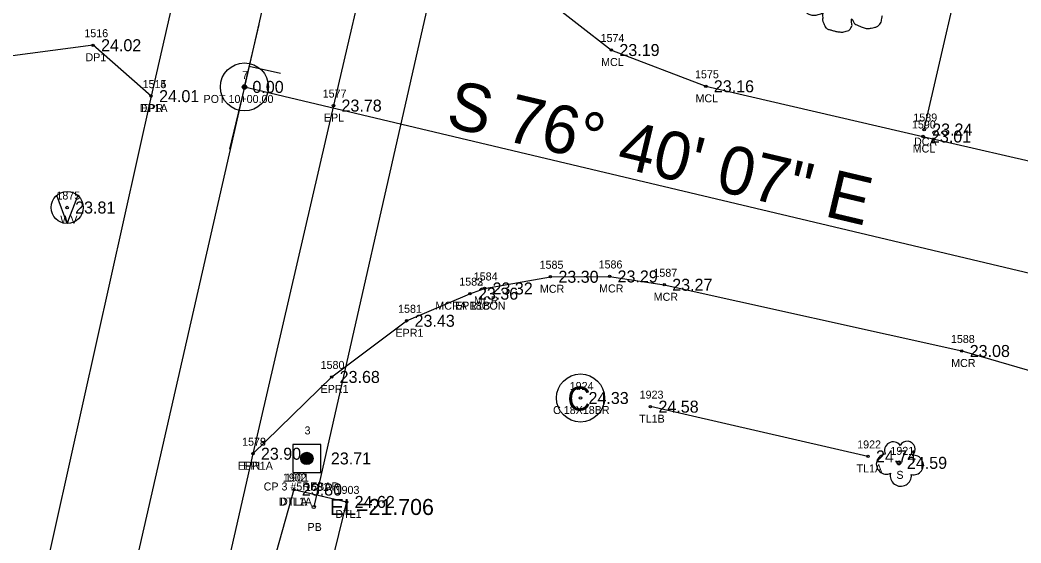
# Model space of a CAD drawing. Extents: x 2654414 to 2656963, y 761776 to 764965.
# Drawn here: x 2655582.6 to 2655707.7, y 762727.3 to 762792.6 of the extents above; entities that cross this region are included whole.
import ezdxf

# ---------------------------------------------------------------- set-up
doc = ezdxf.new("R2010")
doc.units = 0
for name, color, linetype in [('Default', 7, 'Continuous'), ('RD_EX_BldgApp', 7, 'Continuous'), ('RD_EX_BldgApp_txCode', 7, 'Continuous'), ('RD_EX_Conc', 7, 'Continuous'), ('RD_EX_Conc_txCode', 7, 'Continuous'), ('RD_EX_DR_Pipe', 7, 'Continuous'), ('RD_EX_DR_Pipe_txCode', 7, 'Continuous'), ('RD_EX_Driveway', 7, 'Continuous'), ('RD_EX_Driveway_txCode', 7, 'Continuous'), ('RD_EX_H2O', 7, 'Continuous'), ('RD_EX_H2O_txCode', 7, 'Continuous'), ('RD_EX_Road', 7, 'Continuous'), ('RD_EX_Road_txCode', 7, 'Continuous'), ('RD_EX_TX_BldgApp_ELEV', 7, 'Continuous'), ('RD_EX_TX_Conc_ELEV', 7, 'Continuous'), ('RD_EX_TX_Driveway_ELEV', 7, 'Continuous'), ('RD_EX_TX_H2O_ELEV', 7, 'Continuous'), ('RD_EX_TX_Road_ELEV', 7, 'Continuous'), ('RD_EX_TX_UT_ELEV', 7, 'Continuous'), ('RD_EX_TX_VEG_ELEV', 7, 'Continuous'), ('RD_EX_UT', 7, 'Continuous'), ('RD_EX_UT_txCode', 7, 'Continuous'), ('RD_EX_VEG', 7, 'Continuous'), ('RD_EX_VEG_txCode', 7, 'Continuous'), ('RD_HC_Cl', 7, 'Continuous'), ('RD_HC_Data', 7, 'Continuous'), ('RD_HC_Data_Tic', 7, 'Continuous'), ('RD_HC_Survey', 7, 'Continuous'), ('RD_HC_Survey_ELEV', 7, 'Continuous'), ('RD_HC_Survey_txCode', 7, 'Continuous'), ('RD_HC_txCode', 7, 'Continuous'), ('RD_SMD_Locator', 7, 'Continuous'), ('RD_TX_Pipe_ElevEX', 7, 'Continuous')]:
    doc.layers.add(name, color=color, linetype=linetype)

msp = doc.modelspace()

# ---------------------------------------------------------------- linework, layer by layer
at = {"layer": 'Default'}
msp.add_line((2656050.51, 764712.37), (2655383.26, 761787.51), dxfattribs=at)
at = {"layer": 'RD_EX_BldgApp'}
msp.add_circle((2655652.64, 762745.39), 3, dxfattribs=at)
at = {"layer": 'RD_EX_Conc'}
for points in [[(2655695.58, 762778.92), (2655701.44, 762804.38), (2655697.59, 762810.88), (2655698.83, 762816.69)], [(2655647.95, 762795.55), (2655656.5, 762788.85), (2655668.3, 762784.32), (2655695.43, 762778.05), (2655712.44, 762774.14), (2655737.03, 762767.62), (2655754.84, 762760.94), (2655757.41, 762759.82), (2655785.93, 762744.56)], [(2655638.83, 762758.42), (2655640.65, 762759.07), (2655648.88, 762760.53), (2655656.27, 762760.57), (2655663.1, 762759.53), (2655700.27, 762751.26), (2655744.39, 762738.46), (2655772.67, 762723.5), (2655774.32, 762722.61)]]:
    msp.add_lwpolyline(points, dxfattribs=at)
at = {"layer": 'RD_EX_DR_Pipe'}
msp.add_line((2655640.05, 762823.04), (2655619.31, 762731.78), dxfattribs=at)
at = {"layer": 'RD_EX_Driveway'}
msp.add_lwpolyline([(2655598.99, 762783.09), (2655591.74, 762789.45), (2655575.98, 762787.38), (2655565.19, 762780.33), (2655555.27, 762759.9), (2655550.24, 762730.01), (2655544.34, 762701.07), (2655531.32, 762637.94), (2655527.7, 762630.48), (2655527.21, 762614.18), (2655533.68, 762601.37), (2655541.26, 762592.29), (2655549.19, 762591.56), (2655556.36, 762593.84)], dxfattribs=at)
at = {"layer": 'RD_EX_H2O'}
for points in [[(2655616.83, 762733.96), (2655623.42, 762732.41), (2655617.05, 762706.39), (2655607.13, 762649.27), (2655597.13, 762609.55), (2655592.83, 762601.92), (2655590.72, 762602.48), (2655588.85, 762603.42), (2655588.37, 762607.98)], [(2655616.83, 762733.96), (2655609.4, 762707.61), (2655588.37, 762607.98)]]:
    msp.add_lwpolyline(points, dxfattribs=at)
at = {"layer": 'RD_EX_Road'}
for points in [[(2655700.99, 763232.28), (2655693.55, 763198.57), (2655671.65, 763102.04), (2655649.04, 763001.06), (2655627.27, 762906.23), (2655605, 762809.37), (2655598.99, 762783.09), (2655583.65, 762714.14), (2655561.97, 762618.32), (2655556.36, 762593.84), (2655548.11, 762557.14), (2655540.1, 762522.48), (2655518.03, 762425.04), (2655496.48, 762329.56), (2655475.55, 762236.62), (2655473.2, 762226.14), (2655466.57, 762197.5), (2655460.06, 762168.16), (2655454.26, 762143.78), (2655432.5, 762049.88), (2655410.7, 761955.51), (2655388.17, 761858.43), (2655373.5, 761793.95)], [(2655670.04, 762995.18), (2655648.57, 762900.67), (2655631.27, 762824.03), (2655626.67, 762802.87), (2655621.78, 762781.91), (2655611.71, 762738.43), (2655604.93, 762708.62), (2655582.64, 762610.54), (2655576.46, 762583.32), (2655561.41, 762517.24), (2655539.15, 762414.81), (2655531.98, 762386.15), (2655517.98, 762324.29), (2655508.17, 762280.15), (2655501.46, 762251.6), (2655496.92, 762232.09), (2655477.2, 762144.97), (2655472.14, 762122.52), (2655453.74, 762045.1), (2655431.79, 761949.92), (2655409.76, 761853.25), (2655401.25, 761816.42), (2655394.61, 761787.37)], [(2655611.71, 762738.43), (2655621.55, 762748.02), (2655630.91, 762755.03), (2655638.83, 762758.42)]]:
    msp.add_lwpolyline(points, dxfattribs=at)
at = {"layer": 'RD_EX_UT'}
for q in [(2655587.2, 762770.67), (2655589.82, 762770.64)]:
    msp.add_line((2655588.5, 762767.19), q, dxfattribs=at)
msp.add_circle((2655588.5, 762769.18), 2, dxfattribs=at)
at = {"layer": 'RD_EX_VEG'}
msp.add_line((2655688.56, 762738.09), (2655661.38, 762744.31), dxfattribs=at)
msp.add_circle((2655692.42, 762737.29), 0.25, dxfattribs=at)
for centre, radius, start, end in [((2655691.7, 762738.83), 1.08, 34.9763, 204.756), ((2655693.46, 762738.99), 0.995, 308.7626, 152.0467), ((2655690.86, 762737.13), 1.26, 96.4518, 294.734), ((2655694.26, 762737.01), 1.22, 256.5667, 98.1046), ((2655692.66, 762735.69), 1.32, 166.8827, 5.7589)]:
    msp.add_arc(centre, radius, start, end, dxfattribs=at)
msp.add_spline([(2655686.15, 762805.66), (2655685.85, 762805.69), (2655685.52, 762805.59), (2655685.27, 762805.49), (2655685.05, 762805.41), (2655684.82, 762805.31), (2655684.52, 762805.14), (2655684.3, 762804.94), (2655684.17, 762804.69), (2655684.12, 762804.46), (2655684.07, 762804.19), (2655684.07, 762804.01), (2655683.95, 762803.99), (2655683.8, 762804.01), (2655683.55, 762804.09), (2655683.3, 762804.09), (2655683.05, 762804.09), (2655682.7, 762804.06), (2655682.35, 762804.06), (2655682.08, 762804.01), (2655681.75, 762803.96), (2655681.38, 762803.84), (2655681.03, 762803.71), (2655680.73, 762803.46), (2655680.48, 762802.99), (2655680.35, 762802.64), (2655680.2, 762802.39), (2655680.35, 762801.94), (2655680.53, 762801.59), (2655680.55, 762801.39), (2655680.63, 762800.96), (2655680.73, 762800.74), (2655680.85, 762800.54), (2655680.78, 762800.51), (2655680.4, 762800.46), (2655680.1, 762800.36), (2655679.68, 762800.14), (2655679.45, 762799.91), (2655679.35, 762799.59), (2655679.33, 762799.24), (2655679.23, 762799.04), (2655679.15, 762798.76), (2655679.13, 762798.69), (2655679.08, 762798.36), (2655679.18, 762797.91), (2655679.2, 762797.56), (2655679.33, 762797.34), (2655679.48, 762797.16), (2655679.65, 762796.91), (2655680.05, 762796.69), (2655680.38, 762796.59), (2655680.58, 762796.56), (2655680.4, 762796.06), (2655680.35, 762795.71), (2655680.23, 762795.32), (2655680.23, 762795.24), (2655680.18, 762794.77), (2655680.33, 762794.44), (2655680.4, 762794.07), (2655680.58, 762793.84), (2655680.85, 762793.54), (2655681.18, 762793.32), (2655681.68, 762793.19), (2655682.08, 762793.22), (2655682.65, 762793.39), (2655682.9, 762793.47), (2655682.88, 762793.29), (2655682.9, 762792.92), (2655682.9, 762792.49), (2655683.05, 762792.17), (2655683.15, 762791.89), (2655683.3, 762791.64), (2655683.63, 762791.42), (2655684.02, 762791.34), (2655684.45, 762791.19), (2655684.9, 762791.12), (2655685.4, 762791.09), (2655686, 762791.24), (2655686.27, 762791.37), (2655686.37, 762791.54), (2655686.57, 762791.92), (2655686.52, 762792.14), (2655686.55, 762792.74), (2655686.65, 762792.57), (2655686.82, 762792.22), (2655687.32, 762791.92), (2655687.72, 762791.74), (2655688.2, 762791.59), (2655688.5, 762791.52), (2655688.97, 762791.59), (2655689.35, 762791.67), (2655689.72, 762791.79), (2655690.02, 762792.07), (2655690.2, 762792.34), (2655690.25, 762792.62), (2655690.32, 762792.99), (2655690.37, 762793.17)], degree=3, dxfattribs=at)
at = {"layer": 'RD_HC_Cl'}
for p, q in [((2656050.51, 764712.37), (2655383.26, 761787.51)), ((2655610.65, 762784.24), (2655716.3, 762759.21))]:
    msp.add_line(p, q, dxfattribs=at)
at = {"layer": 'RD_HC_Data'}
for radius in [3, 0.282]:
    msp.add_circle((2655610.65, 762784.24), radius, dxfattribs=at)
at = {"layer": 'RD_HC_Data_Tic'}
for p, q in [((2655610.65, 762784.24), (2655612.49, 762792.03)), ((2655611.24, 762786.84), (2655615.14, 762785.95)), ((2655610.65, 762784.24), (2655608.8, 762776.46))]:
    msp.add_line(p, q, dxfattribs=at)
at = {"layer": 'RD_HC_Survey'}
for p, q in [((2655617.7, 762737.66), (2655617.7, 762738.02)), ((2655617.72, 762737.58), (2655617.72, 762738.1)), ((2655617.75, 762737.52), (2655617.75, 762738.16)), ((2655617.77, 762737.47), (2655617.77, 762738.21)), ((2655617.8, 762737.43), (2655617.8, 762738.25)), ((2655617.82, 762737.39), (2655617.82, 762738.29)), ((2655617.85, 762737.36), (2655617.85, 762738.32)), ((2655617.87, 762737.33), (2655617.87, 762738.35)), ((2655617.9, 762737.3), (2655617.9, 762738.38)), ((2655617.92, 762737.28), (2655617.92, 762738.4)), ((2655617.95, 762737.25), (2655617.95, 762738.42)), ((2655617.97, 762737.23), (2655617.97, 762738.44)), ((2655618, 762737.22), (2655618, 762738.46)), ((2655618.02, 762737.2), (2655618.02, 762738.48)), ((2655618.05, 762737.18), (2655618.05, 762738.5)), ((2655618.07, 762737.17), (2655618.07, 762738.51)), ((2655618.09, 762737.16), (2655618.09, 762738.52)), ((2655618.12, 762737.14), (2655618.12, 762738.54)), ((2655618.14, 762737.13), (2655618.14, 762738.55)), ((2655618.17, 762737.12), (2655618.17, 762738.56)), ((2655618.19, 762737.11), (2655618.19, 762738.57)), ((2655618.22, 762737.1), (2655618.22, 762738.57)), ((2655618.24, 762737.1), (2655618.24, 762738.58)), ((2655618.27, 762737.09), (2655618.27, 762738.59)), ((2655618.29, 762737.09), (2655618.29, 762738.59)), ((2655618.32, 762737.08), (2655618.32, 762738.6)), ((2655618.34, 762737.08), (2655618.34, 762738.6)), ((2655618.37, 762737.07), (2655618.37, 762738.6)), ((2655618.39, 762737.07), (2655618.39, 762738.61)), ((2655618.42, 762737.07), (2655618.42, 762738.61)), ((2655618.44, 762737.07), (2655618.44, 762738.61)), ((2655618.47, 762737.07), (2655618.47, 762738.61)), ((2655618.49, 762737.07), (2655618.49, 762738.61)), ((2655618.52, 762737.07), (2655618.52, 762738.61)), ((2655618.54, 762737.08), (2655618.54, 762738.6)), ((2655618.56, 762737.08), (2655618.56, 762738.6)), ((2655618.59, 762737.08), (2655618.59, 762738.6)), ((2655618.61, 762737.09), (2655618.61, 762738.59)), ((2655618.64, 762737.09), (2655618.64, 762738.58)), ((2655618.66, 762737.1), (2655618.66, 762738.58)), ((2655618.69, 762737.11), (2655618.69, 762738.57)), ((2655618.71, 762737.12), (2655618.71, 762738.56)), ((2655618.74, 762737.13), (2655618.74, 762738.55)), ((2655618.76, 762737.14), (2655618.76, 762738.54)), ((2655618.79, 762737.15), (2655618.79, 762738.53)), ((2655618.81, 762737.16), (2655618.81, 762738.52)), ((2655618.84, 762737.18), (2655618.84, 762738.5)), ((2655618.86, 762737.19), (2655618.86, 762738.49)), ((2655618.89, 762737.21), (2655618.89, 762738.47)), ((2655618.91, 762737.23), (2655618.91, 762738.45)), ((2655618.94, 762737.25), (2655618.94, 762738.43)), ((2655618.96, 762737.27), (2655618.96, 762738.41)), ((2655618.99, 762737.29), (2655618.99, 762738.39)), ((2655619.01, 762737.31), (2655619.01, 762738.36)), ((2655619.04, 762737.34), (2655619.04, 762738.34)), ((2655619.06, 762737.37), (2655619.06, 762738.3)), ((2655619.08, 762737.41), (2655619.08, 762738.27)), ((2655619.11, 762737.45), (2655619.11, 762738.23)), ((2655619.13, 762737.49), (2655619.13, 762738.19)), ((2655619.16, 762737.55), (2655619.16, 762738.13)), ((2655619.18, 762737.62), (2655619.18, 762738.06)), ((2655619.21, 762737.73), (2655619.21, 762737.95))]:
    msp.add_line(p, q, dxfattribs=at)
msp.add_lwpolyline([(2655620.2, 762739.59), (2655616.7, 762739.59), (2655616.7, 762736.09), (2655620.2, 762736.09)], close=True, dxfattribs=at)
msp.add_circle((2655618.45, 762737.84), 0.769, dxfattribs=at)
at = {"layer": 'RD_SMD_Locator'}
for centre, radius in [((2655591.74, 762789.45), 0.15), ((2655656.5, 762788.85), 0.15), ((2655610.65, 762784.24), 0.15), ((2655668.3, 762784.32), 0.15), ((2655598.99, 762783.09), 0.15), ((2655598.99, 762783.09), 0.15), ((2655621.78, 762781.91), 0.15), ((2655695.58, 762778.92), 0.15), ((2655695.43, 762778.05), 0.15), ((2655588.5, 762769.18), 0.15), ((2655648.88, 762760.53), 0.15), ((2655656.27, 762760.57), 0.15), ((2655640.65, 762759.07), 0.15), ((2655663.1, 762759.53), 0.15), ((2655638.83, 762758.42), 0.15), ((2655638.83, 762758.42), 0.15), ((2655630.91, 762755.03), 0.15), ((2655700.27, 762751.26), 0.15), ((2655621.55, 762748.02), 0.15), ((2655652.64, 762745.39), 0.15), ((2655661.38, 762744.31), 0.15), ((2655611.71, 762738.43), 0.15), ((2655611.71, 762738.43), 0.15), ((2655618.45, 762737.84), 0.15), ((2655688.56, 762738.09), 0.15), ((2655692.42, 762737.29), 0.15), ((2655616.83, 762733.96), 0.15), ((2655616.83, 762733.96), 0.15), ((2655623.42, 762732.41), 0.15), ((2655619.31, 762731.78), 0.2)]:
    msp.add_circle(centre, radius, dxfattribs=at)

# ---------------------------------------------------------------- texts
at = {"layer": 'RD_EX_BldgApp'}
msp.add_text('C', height=3, dxfattribs=at).set_placement((2655651.01, 762743.82))
at = {"layer": 'RD_EX_BldgApp_txCode'}
for s, p in [('1924', (2655651.29, 762746.39)), ('C 18X18BR', (2655649.21, 762743.39))]:
    msp.add_text(s, height=1, dxfattribs=at).set_placement(p)
at = {"layer": 'RD_EX_Conc_txCode'}
for s, p in [('1574', (2655655.15, 762789.85)), ('MCL', (2655655.21, 762786.85)), ('1575', (2655666.95, 762785.32)), ('MCL', (2655667.01, 762782.32)), ('1590', (2655694.05, 762779.05)), ('1589', (2655694.23, 762779.92)), ('DCA', (2655694.31, 762776.92)), ('MCL', (2655694.14, 762776.05)), ('1585', (2655647.53, 762761.53)), ('1586', (2655654.9, 762761.57)), ('1587', (2655661.75, 762760.53)), ('1583', (2655637.49, 762759.42)), ('1584', (2655639.3, 762760.07)), ('MCR', (2655647.57, 762758.53)), ('MCR', (2655654.96, 762758.57)), ('MCRA 18CON', (2655634.5, 762756.42)), ('MCR', (2655639.34, 762757.07)), ('MCR', (2655661.78, 762757.53)), ('1588', (2655698.92, 762752.26)), ('MCR', (2655698.95, 762749.26))]:
    msp.add_text(s, height=1, dxfattribs=at).set_placement(p)
at = {"layer": 'RD_EX_DR_Pipe_txCode'}
for s, p in [('1631', (2655618.22, 762733.78)), ('PB', (2655618.53, 762728.78))]:
    msp.add_text(s, height=1, dxfattribs=at).set_placement(p)
at = {"layer": 'RD_EX_Driveway_txCode'}
for s, p in [('1516', (2655590.65, 762790.45)), ('DP1', (2655590.79, 762787.45)), ('1515', (2655597.93, 762784.09)), ('DP1A', (2655597.56, 762781.09))]:
    msp.add_text(s, height=1, dxfattribs=at).set_placement(p)
at = {"layer": 'RD_EX_H2O_txCode'}
for s, p in [('1902', (2655615.45, 762734.96)), ('1901', (2655615.73, 762734.96)), ('1903', (2655622.04, 762733.41)), ('DTL1A', (2655614.93, 762731.96)), ('DTLA', (2655615.1, 762731.96)), ('DTL1', (2655622.01, 762730.41))]:
    msp.add_text(s, height=1, dxfattribs=at).set_placement(p)
at = {"layer": 'RD_EX_Road_txCode'}
for s, p in [('1514', (2655597.93, 762784.09)), ('1577', (2655620.43, 762782.91)), ('EPR', (2655597.76, 762781.09)), ('EPL', (2655620.58, 762779.91)), ('1582', (2655637.49, 762759.42)), ('EPR1B', (2655636.97, 762756.42)), ('1581', (2655629.85, 762756.03)), ('EPR1', (2655629.52, 762753.03)), ('1580', (2655620.17, 762749.02)), ('EPR1', (2655620.16, 762746.02)), ('1578', (2655610.36, 762739.43)), ('1579', (2655610.36, 762739.43)), ('EPR1A', (2655609.82, 762736.43)), ('EPL', (2655610.5, 762736.43))]:
    msp.add_text(s, height=1, dxfattribs=at).set_placement(p)
at = {"layer": 'RD_EX_TX_BldgApp_ELEV'}
msp.add_text('24.33', height=1.5, dxfattribs=at).set_placement((2655653.64, 762744.64))
at = {"layer": 'RD_EX_TX_Conc_ELEV'}
for s, p in [('23.19', (2655657.5, 762788.1)), ('23.16', (2655669.3, 762783.57)), ('23.01', (2655696.43, 762777.3)), ('23.24', (2655696.58, 762778.17)), ('23.30', (2655649.88, 762759.78)), ('23.29', (2655657.27, 762759.82)), ('23.27', (2655664.1, 762758.78)), ('23.36', (2655639.83, 762757.67)), ('23.32', (2655641.65, 762758.32)), ('23.08', (2655701.27, 762750.51))]:
    msp.add_text(s, height=1.5, dxfattribs=at).set_placement(p)
at = {"layer": 'RD_EX_TX_Driveway_ELEV'}
for s, p in [('24.02', (2655592.74, 762788.7)), ('24.01', (2655599.99, 762782.34))]:
    msp.add_text(s, height=1.5, dxfattribs=at).set_placement(p)
at = {"layer": 'RD_EX_TX_H2O_ELEV'}
for s, p in [('23.80', (2655617.83, 762733.21)), ('23.80', (2655617.83, 762733.21)), ('24.62', (2655624.42, 762731.66))]:
    msp.add_text(s, height=1.5, dxfattribs=at).set_placement(p)
at = {"layer": 'RD_EX_TX_Road_ELEV'}
for s, p in [('24.01', (2655599.99, 762782.34)), ('23.78', (2655622.78, 762781.16)), ('23.36', (2655639.83, 762757.67)), ('23.43', (2655631.91, 762754.28)), ('23.68', (2655622.55, 762747.27)), ('23.90', (2655612.71, 762737.68)), ('23.90', (2655612.71, 762737.68))]:
    msp.add_text(s, height=1.5, dxfattribs=at).set_placement(p)
at = {"layer": 'RD_EX_TX_UT_ELEV'}
msp.add_text('23.81', height=1.5, dxfattribs=at).set_placement((2655589.5, 762768.43))
at = {"layer": 'RD_EX_TX_VEG_ELEV'}
for s, p in [('24.58', (2655662.38, 762743.56)), ('24.74', (2655689.56, 762737.34)), ('24.59', (2655693.42, 762736.54))]:
    msp.add_text(s, height=1.5, dxfattribs=at).set_placement(p)
at = {"layer": 'RD_EX_UT_txCode'}
for s, p in [('1875', (2655587.16, 762770.18)), ('WV', (2655587.64, 762767.18))]:
    msp.add_text(s, height=1, dxfattribs=at).set_placement(p)
at = {"layer": 'RD_EX_VEG_txCode'}
for s, p in [('1923', (2655660.03, 762745.31)), ('TL1B', (2655659.97, 762742.31)), ('1922', (2655687.21, 762739.09)), ('1921', (2655691.36, 762738.29)), ('TL1A', (2655687.13, 762736.09)), ('S', (2655692.11, 762735.29))]:
    msp.add_text(s, height=1, dxfattribs=at).set_placement(p)
at = {"layer": 'RD_HC_Data'}
msp.add_text('S 76%%d 40\' 07" E', height=6, rotation=346.6686, dxfattribs=at).set_placement((2655635.64, 762779.35))
at = {"layer": 'RD_HC_Survey_ELEV'}
for s, p in [('0.00', (2655611.65, 762783.49)), ('23.71', (2655621.45, 762737.09))]:
    msp.add_text(s, height=1.5, dxfattribs=at).set_placement(p)
at = {"layer": 'RD_HC_Survey_txCode'}
for s, p in [('3', (2655618.16, 762740.84)), ('CP 3 #5REBAR', (2655613.05, 762733.84))]:
    msp.add_text(s, height=1, dxfattribs=at).set_placement(p)
at = {"layer": 'RD_HC_txCode'}
for s, p in [('7', (2655610.36, 762785.24)), ('POT 10+00.00', (2655605.54, 762782.24))]:
    msp.add_text(s, height=1, dxfattribs=at).set_placement(p)
at = {"layer": 'RD_TX_Pipe_ElevEX'}
msp.add_text('EL=21.706', height=2, dxfattribs=at).set_placement((2655621.31, 762730.78))

doc.saveas('drawing.dxf')
